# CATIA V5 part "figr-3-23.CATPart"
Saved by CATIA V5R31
Part number: figr-3-23
Bounding box of the stored display mesh (mm): x 0 to 0, y -2187335.75 to 2141537, z -681609 to 2530522.25
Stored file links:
  D:\PROJECTS\Project 2021\US EDITION\CATIA V5 6R 2021\Resources\Part Files\c03_catia_v5_6r2021_prt\figr-3-23.CATPart
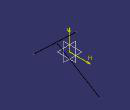
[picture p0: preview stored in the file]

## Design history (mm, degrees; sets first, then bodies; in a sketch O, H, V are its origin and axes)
Body1 (main body)
  Sketch1 on yz-plane, origin (0, 0, 0), H (0, 1, 0), V (0, 0, 1)
    line L1 through (-830059.7691, 1160197.0782) direction (0.7237, 0.6901)
    line L2 through (299240.8462, 476164.2676) direction (0.8467, -0.5321)
    line L3 (-18.0725, -9.9702) -> (3.3205, 10.401)
    line L4 (15.39, -12.4607) -> (-6.6544, 0.9026)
